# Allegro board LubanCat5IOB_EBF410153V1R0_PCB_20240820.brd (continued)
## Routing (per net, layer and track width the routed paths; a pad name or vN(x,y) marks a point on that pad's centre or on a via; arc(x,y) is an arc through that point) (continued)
VBUS5V0_TYPEC: length 27.4
  TOP w0.173: v1(24.9,99.19) v1(24.9,99.99) ; v1(27.4,99.19) v1(27.4,99.99)
  TOP w0.203: J8.A4 27.16,96.67 27.4,96.91 J8.B9 v1(27.4,99.19) ; v1(24.9,99.19) J8.B4 24.9,96.91 24.66,96.67 J8.A9
  TOP w0.254: U5.2 17.52,86.37 C74.1 17.14,88.41 17.78,89.04 17.78,90.8 v1(18.17,91.19)
  BOTTOM w0.152: v1(15.65,96.88) 15.17,96.41 C87.1 C88.1 15.17,88.59 15.23,88.54 U6.1
  BOTTOM w0.508: v1(18.17,91.19) 17.5,91.86 15.49,91.86
  vias: v1(14.65,97.88) v1(14.65,96.88) v1(15.65,97.88) v1(24.9,100.79) v1(27.4,100.79)
VCC3V3_PCIECLK: length 41.3
  TOP w0.254: C163.1 116.2,43.81 v1(115.84,44.18) 115.49,43.83 U26.1
  BOTTOM w0.381: 110.52,46.96 110.52,39.38 110.9,39 118.87,39 119.3,38.57 125.27,38.57 v1(126.26,37.58) ; 110.52,46.96 110.93,47.38 112.93,47.38 113.29,47.01 R223.1 ; 110.52,46.96 109.47,48.01 R235.1 C168.1 ; R225.1 R223.1 ; R223.1 R224.1 R226.1 116.02,45.98 116.59,45.4 C162.1 116.19,43.83 v1(115.84,44.18)
  vias: v1(127.26,37.58)
VCC3V3_PCIEX4: length 2.7
  TOP w0.254: C180.1 v1(27.56,43.81)
  BOTTOM w0.254: C194.2 R249.2 20.12,44.19
  vias: v1(26.56,43.81) v1(26.56,42.81) v1(27.56,42.81) v1(28.56,43.81) v1(28.56,42.81)
VCC3V3_SD_S3: length 19.2
  TOP w0.254: v1(150.51,19.83) 151.22,20.54 152.6,20.54 C10.1 153.97,20.54 155.15,20.54 D23.1 156.2,21.59 J24.4 ; v1(150.51,14.75) 151.15,14.11 152.65,14.11 C9.1 R285.2
  BOTTOM w0.254: v1(150.51,19.83) v1(150.51,14.75)
VCC4V0_SYS: length 304.1
  TOP w0.254: U2.5 17.78,25.52 C27.1 ; v1(166.98,96.11) 167.86,95.23 167.86,85.25 168.4,84.71 170.61,84.71 171.12,84.2 171.12,32.49 170.51,31.88 166.14,31.88 165.51,31.24 165.51,14.27 165.13,13.89 157.21,13.89 156.52,13.21 148.41,13.21 148.03,12.83 148.03,9.24 147.44,8.66 30.3,8.66 29.79,9.16 29.79,13.85 v1(29.57,14.07) ; R362.1 47.37,14.23 45.98,12.84 36.96,12.84 36.7,13.09 v2(36.7,13.88) 36.7,21.15 37.21,21.66 37.21,22.62 ; R11.1 v1(149.99,98.55)
  BOTTOM w0.254: R12.1 21.33,31.77 C20.2 21.34,24.86 21.79,24.4 26.09,24.4 26.53,23.95 v1(26.53,22.32) ; v2(36.7,13.88) 36.51,14.07 v1(29.57,14.07) ; v1(149.99,98.55) 149.99,99.79 150.5,100.29 164.98,100.29 165.81,99.47 165.81,96.62 166.32,96.11 v1(166.98,96.11)
VCC5V0_HDMI_RX: length 40.1
  TOP w0.254: R193.1 121.24,76.97 D40.2 ; Q27.2 131.89,83.49 R213.1 132.34,85.84 131.83,86.35 121.79,86.35 121.25,85.8 121.25,81.61 121.18,81.54 121.18,80.28 v1(121.11,80.21)
  BOTTOM w0.381: v1(122.11,80.21) v1(121.11,80.21) 117.73,80.21 117.07,80.87 117.07,82.04 116.31,82.8 114.94,82.8 114.31,83.43 C155.1 D45.2 111.76,84.58 111.45,84.27 110.2,84.27 109.83,84.65 J18.18
VCC5V0_USB20_HOST: length 9.5
  BOTTOM w0.508: J9.10 126.89,90.18 128.02,91.31 128.02,93.59 C286.1 C285.1
VCC5V0_USB20_HUB: length 11.5
  BOTTOM w0.508: C92.1 145.3,92.2 J10.7 J10.1
VCC5V0_USB30_OTG: length 15.9
  ART03 w0.254: J9.1 126.37,97.74 126.8,98.17 127.89,98.17 v1(128.65,98.93)
  BOTTOM w0.254: R150.1 v1(128.65,98.93)
  BOTTOM w0.508: J9.1 126.37,94.2 125.4,95.17 122.24,95.17 121.66,95.76 C91.1 C90.1
VCC5V0_USB_S0: length 21.3
  TOP w0.254: C8.1 27.56,55.42 ; U5.13 19.69,88.65 C72.1 v1(19.42,89.67) ; v1(20.46,89.67) C73.1 20.19,88.65 U5.12
  ART04 w0.254: v1(26.56,54.42) v1(27.36,54.42) v1(28.16,54.42) ; v1(26.56,55.42) v1(27.36,55.42) v1(28.16,55.42)
  BOTTOM w0.254: R4.2 C7.2 19.05,56.9 19.8,56.9 20.19,57.29 20.19,58.92 20.55,59.28 26.06,59.28 26.39,58.94 26.39,57.23 26.72,56.9
  vias: v1(5.7,91.11) v1(5.7,90.31) v1(5.7,89.51) v1(5.7,88.71) v1(5.7,87.91) v1(44.5,97.33) v1(44.5,96.33) v1(44.5,95.53) v1(44.5,94.73) v1(44.5,93.93) v1(44.5,93.13) v1(121.16,101.75) v1(121.16,100.95) v1(122.81,101.73) v1(122.81,100.93) v1(124.46,101.75) v1(124.46,100.95) v1(126.46,101.75) v1(141.1,101.5) v1(141.1,100.5) v1(142.1,100.5) v3(14.43,86.1) v3(15.23,86.1) v3(16.03,86.1) v3(16.03,85.3)
VCC12V_PCIEX4: length 3
  ART03 w0.254: v1(28.56,38.81) v1(27.56,38.81) v1(26.56,38.81) v1(26.56,39.81) 26.53,39.84
  vias: v1(27.56,39.81) v1(28.56,39.81)
VCC_1V8_S0: length 388.6
  TOP w0.203: J1.21 J1.22 46.47,14.39
  TOP w0.254: v1(111.76,73.37) 112.17,72.96 112.17,70.37 v1(111.68,69.89) ; 46.47,14.39 45.94,13.86 v2(39.7,13.86) ; v1(146.41,33.18) 146.65,33.43 Q33.1 ; R381.2 v1(63.25,73.67) ; v1(141.54,33.82) 141.69,33.97 Q34.1 ; R210.1 118.49,75.71 119.48,74.72 v1(119.48,74.31)
  ART03 w0.254: v2(38.7,13.86) 38.7,12.09 39.27,11.52 39.27,8.98 38.76,8.47 18.54,8.47 18.24,8.78 18.24,15.31 17.86,15.69 11.46,15.69 10.95,16.19 v1(10.95,16.22)
  ART03 w0.508: v1(77.37,39.69) 78.46,39.69 80.7,37.45 v1(95.32,37.45) v1(96.32,37.45)
  ART04 w0.305: v1(15.58,49.4) 15.07,48.89 15.07,46.32 14.1,45.35 11.18,45.35 10.44,44.62 10.44,20.89 10.95,20.39 v1(10.95,16.22)
  ART04 w0.381: v1(146.41,33.18) 142.18,33.18 v1(141.54,33.82) ; v1(157.1,36.92) 157.1,41.82 143.36,55.56 120.42,55.56 119.84,56.15 119.84,63.11 120.73,64 120.73,65.98 120.35,66.36 118.78,66.36 117.88,67.25 117.88,70.2 119.48,71.8 v1(119.48,74.31) 118.81,74.98 112.14,74.98 111.76,74.6 v1(111.76,73.37) 111.35,72.96 110.03,72.96 109.27,72.2 109.27,70.73 108.79,70.25 105.33,70.25 104.57,71.01 104.57,75.91 103.81,76.67 89.84,76.67 89.08,75.91 89.08,70.65 88.32,69.89 82.07,69.89 81.31,70.65 81.31,72.71 80.67,73.34 63.58,73.34 v1(63.25,73.67)
  ART04 w0.508: v1(146.41,33.18) v1(147.21,33.18) 147.65,33.63 147.65,34.79 146.89,35.55 146.08,35.55 145.31,36.31 145.31,40.25 144.4,41.16 126.59,41.16 123.67,38.24 98.53,38.24 97.74,37.45 v1(96.32,37.45) ; v1(43.59,27.62) v1(43.59,28.62) 44.17,29.21 44.17,36.59 45.19,37.61 49.28,37.61 51,39.33 74.09,39.33 74.45,39.69 v1(76.37,39.69) v1(77.37,39.69)
  BOTTOM w0.254: R273.2 16.26,50.09 v1(15.58,49.4) ; R175.1 120.89,70.62 121.41,71.14 121.41,73.28 121.04,73.65 R174.1 119.61,74.31 v1(119.48,74.31) ; Q23.1 111.05,69.66 R191.1 111.68,69.38 v1(111.68,69.89) ; v1(141.54,33.82) 142.27,34.55 R332.1 ; Q15.1 111.05,73.09 R172.1 111.76,72.89 v1(111.76,73.37) ; v1(146.41,33.18) 146.69,33.46 R329.1
  vias: v1(157.1,35.92)
VCC_1V8_S3: length 351.7
  TOP w0.203: J1.19 J1.20 46.07,15.03
  TOP w0.254: R284.1 149.38,16.51 149.38,24.07 151.87,26.56 154.74,26.56 155.27,27.1 155.27,28 154.91,28.36 152.1,28.36 151.59,28.87 v1(151.59,39.89) ; v2(39.7,14.86) 40.04,14.52 45.56,14.52 46.07,15.03
  TOP w0.381: v1(34,30.12) 43.77,30.12 v1(45.2,28.69)
  ART03 w0.254: v1(5.99,95.62) 6.76,96.38 19.1,96.38 19.61,95.87 19.61,93.51 20.14,92.98 30.32,92.98 31.15,93.82 34.77,93.82 35.2,94.25 35.2,100.22 35.46,100.47 40.36,100.47 v1(41.4,101.51)
  ART03 w0.508: v1(82.85,36.51) 95.1,36.51 v1(95.35,36.26)
  ART04 w0.381: v2(39.7,14.86) v2(38.7,14.86) 38.21,14.37 36.92,14.37 36.67,14.62 34.82,14.62 34.06,15.38 34.06,18.42 34.59,18.96 34.59,29.53 v1(34,30.12) 34.59,30.71 34.59,34.56 33.99,35.17 31.06,35.17 30.3,35.93 30.3,50.66 29.62,51.35 27.43,51.35 26.59,52.19 16.87,52.19 16.1,52.95 16.1,56.43 15.34,57.19 7.47,57.19 6.5,56.23 3.17,56.23 2.41,56.99 2.41,58.84 1.4,59.86 1.4,94.73 1.88,95.21 5.59,95.21 v1(5.99,95.62) ; v1(82.85,36.51) 78.28,36.51 76.71,38.09 72.9,38.09 71.04,36.24 45.97,36.24 45.2,35.47 v1(45.2,28.69) ; v1(118.59,33.44) 118.59,36.21 117.83,36.97 98.86,36.97 98.15,36.26 v1(95.35,36.26)
  BOTTOM w0.254: v1(151.59,39.89) 150.62,38.93 137.74,38.93 137.08,38.27 137.08,34.94 136.58,34.43 132.18,34.43 129.72,31.97 120.07,31.97 v1(118.59,33.44) 118.59,33.65 R276.1 119.4,34.44 R3.1 ; R119.1 v1(41.4,101.51)
VCC_3V3_S0: length 396.1
  TOP w0.254: R198.1 130.17,84.84 129.79,85.22 127.36,85.22 126.86,84.72 ; R198.1 130.83,83.95 v1(131.06,84.18) ; R198.1 130.49,83.62 Q25.1 ; R356.1 v1(87.12,13.86) ; R356.1 R359.1 R358.1 ; R356.1 R357.1 ; v1(11.18,56.39) 11.18,58.66 7.16,62.68 v1(7.16,64.02) ; 126.86,84.72 R196.1 127.19,83.62 Q24.1 ; 126.86,84.72 126.22,85.36 123.9,85.36 123.56,85.02 R199.1 123.89,83.62 Q26.1 ; R361.1 R360.1 76.32,14.76 75.95,15.13 v1(75.44,15.13) ; U47.5 v1(127.38,26.8) ; Q6.1 83.63,72.1 R151.1 84.08,70.58 83.57,70.08 81.54,70.08 81.03,70.58 R170.1 ; v1(10.44,72.33) 10.52,72.25 10.52,68.42 9.21,67.11 9.21,64.7 v1(8.51,64) ; R128.1 v1(152.92,99.31) ; R328.1 v1(9.28,40.52) ; U45.5 v1(119.25,26.8)
  TOP w0.381: R170.1 79.51,71.64 R363.2 v1(79.5,69.74) ; D46.2 133.53,77.21 v1(132.78,77.21) ; v1(62.19,82.13) 62.14,82.18 R383.2 ; v1(78.47,83.13) 78.86,82.74 R364.2
  ART03 w0.254: v1(152.92,99.31) 148.29,99.31 147.78,98.8 147.78,96.66 147.32,96.2 133.05,96.2 132.69,95.85 132.69,88.53 132.21,88.05 v1(131.06,88.05)
  ART04 w0.254: v1(78.47,83.13) 78.11,82.77 62.83,82.77 v1(62.19,82.13) ; v1(11.18,56.39) 11.95,55.62 13.69,55.62 14.1,55.21 14.1,51.87 ; v1(9.28,40.52) 9.09,40.71 9.09,50.56 9.5,50.97 10.11,50.97 10.52,51.37 13.61,51.37 14.1,51.87 ; 14.1,51.87 14.61,51.36 26.05,51.36 26.56,50.85 v1(26.56,49.68)
  ART04 w0.381: 34.47,9.97 J44.5 ; J44.5 33.75,10.7 ; J44.5 35.2,10.7 ; J44.5 34.47,11.43
  ART04 w0.508: v1(93.6,73.93) 94.61,72.91 v1(94.61,67.71) 94.61,62.78 95.12,62.27 109.45,62.27 109.96,62.78 v1(109.96,64.77) v1(109.96,65.77) 110.54,66.35 110.54,71.13 110.97,71.57 113.2,71.57 113.92,70.85 v1(113.92,69.21) v1(113.92,64.65) 113.92,55.64 114.94,54.62 v1(122.89,54.62) v1(123.89,54.62) 143.15,54.62 155.85,41.92 155.85,33.03 156.57,32.32 156.57,20.42 155.7,19.55 155.7,17.77 154.61,16.68 153.67,16.68 152.3,15.31 148.26,15.31 147.24,16.32 147.24,21.96 146.74,22.47 145.21,22.47 ; v1(132.78,77.21) v1(132.78,78.01) 132.34,78.45 ; 132.34,78.45 122.91,78.45 121.79,77.33 121.79,73.85 121.41,73.47 121.41,63.18 120.65,62.42 120.65,58.77 122.21,57.21 v1(122.85,57.21) v1(123.85,57.21) ; 132.34,78.45 132.54,78.65 132.54,82.71 v1(131.06,84.18) v1(131.06,88.05)
  BOTTOM w0.254: v1(93.6,73.93) 92.96,73.29 R153.1 R154.1 ; L23.1 v1(135.85,28.79) ; R157.1 93.73,66.82 v1(94.61,67.71) 94.74,67.83 R158.1 ; v1(26.56,48.68) 26.33,48.91 20.32,48.91 20.07,49.16 20.07,49.91 19.81,50.16 R272.2 C232.2 ; R179.1 v1(113.92,64.65) ; R65.2 10.74,72.33 v1(10.44,72.33) ; R100.1 C93.1 135.76,74.93 134.97,74.13 133.3,74.13 132.78,74.66 v1(132.78,77.21) ; R330.1 v1(145.61,34.55) ; v1(128.26,32.58) 128.27,32.6 R246.2 ; C216.1 v1(119.25,26.8) ; v1(11.18,56.39) 11.39,56.6 15.29,56.6 R6.2 ; L22.1 143.73,28.66 v1(143.6,28.79) ; C313.1 v1(127.38,26.8) ; v1(140.54,33.82) 140.72,34 R331.1 ; v1(78.47,83.13) 78.23,82.89 78.23,77.94 78,77.71 78,74.31 79.17,73.14 79.17,70.07 v1(79.5,69.74) ; v1(7.16,64.02) 7.19,64 v1(8.51,64) ; R178.1 v1(113.92,69.21)
  BOTTOM w0.305: v1(128.96,21.21) 128.27,21.21 L24.2
  BOTTOM w0.381: R382.2 55.63,71.4 v1(55.63,71.11)
  vias: v1(27.56,49.68) v1(27.56,48.68) v1(28.56,49.68) v1(28.56,48.68) v1(47.35,39.26) v1(48.35,39.26) v1(58.04,59.02) v1(58.04,58.02)
VCC_3V3_S3: length 322
  TOP w0.203: 44.36,16.96 44.87,17.46 J1.14 J1.13
  TOP w0.254: R87.1 18.42,84.13 v1(17.93,84.62) ; R109.1 v1(161.16,96.14) ; v2(39.7,17.86) 40.61,16.96 44.36,16.96 ; R111.2 v1(164.72,96.14) ; v1(137.29,45.23) 136.54,45.23 136.29,45.48 U44.24 ; U33.5 5.83,19.04 C235.1 4.22,18.17 v1(4.19,18.19) ; v1(139.18,45.98) 139.68,46.48 v1(139.68,51.26) ; U34.5 9.63,16.29 9.88,16.55 9.88,17.41 9.63,17.67 C236.1 v1(7.99,18.43) ; R285.1 v1(156.57,14.75)
  TOP w0.381: v1(119.77,39.19) D57.2 v1(119.04,39.93)
  ART03 w0.254: v1(164.72,96.14) 164.87,95.99 164.87,90.8 165.38,90.3 169.49,90.3 169.75,90.04 169.75,88.29 171.15,86.89 171.15,47.47 170.57,46.89
  ART03 w0.381: v1(6.95,86.91) 13.08,86.91 13.46,86.53 13.46,85.26 14.33,84.39 17.7,84.39 v1(17.93,84.62) ; v1(161.49,14.73) 161.49,18.35 162.03,18.89 162.03,30.76 162.99,31.72 170.33,31.72 171.09,32.49 171.09,46.36 170.57,46.89 156.31,46.89 v1(156.13,46.7)
  ART03 w0.508: v1(97.31,38.67) v1(96.31,38.67) 81.18,38.67 78.77,41.09 v1(77.34,41.09)
  ART04 w0.508: v1(97.31,38.67) 98.32,39.69 113.74,39.69 114.33,40.27 118.69,40.27 v1(119.04,39.93) v1(119.77,39.19) 122.45,39.19 125.62,42.36 136.27,42.36 137.29,43.37 v1(137.29,45.23) 138.04,45.98 v1(139.18,45.98) ; v1(38.71,41.21) v1(39.71,41.21) 40.06,41.21 40.94,40.32 73.13,40.32 73.89,41.09 v1(76.34,41.09) v1(77.34,41.09)
  BOTTOM w0.254: v1(161.49,14.73) 160.76,15.47 157.29,15.47 v1(156.57,14.75) ; v1(161.16,96.14) 161.65,96.62 164.24,96.62 v1(164.72,96.14) ; C212.1 C213.1 v1(139.18,45.98) ; C212.1 v1(137.29,45.23) ; C212.1 136.27,47 R353.1 ; v1(17.93,84.62) 18.58,84.62 C81.1 ; v1(156.13,46.7) 155.65,47.19 155.65,48.87 155.33,49.19 153.28,49.19 152.92,48.83 146.83,48.83 146.38,49.27 146.38,50.72 145.85,51.26 v1(139.68,51.26)
  BOTTOM w0.508: v1(38.71,41.21) 38.35,40.86 38.35,18.21 v2(38.7,17.86) v2(39.7,17.86)
  vias: v1(6.95,85.91) v1(6.95,84.65) v1(15.81,65.45) v1(15.81,64.45) v1(16.81,65.45) v1(17.81,65.45) v1(35.1,17.92) v1(36.02,17.9)
VCC_5V0_S0: length 221.7
  TOP w0.254: v1(79.53,99.18) 79.53,93.61 81.05,92.09 81.05,76.24 80.58,75.77 Q14.1 ; v1(162.29,84.3) v1(162.29,83.3) 162.3,83.32 R286.1
  TOP w0.305: U45.3 v1(120.52,29.08) ; U47.3 v1(128.65,29.08)
  ART04 w1.016: J44.3 40.51,8.66 156.12,8.66 157.38,9.92 157.38,12.41 158.82,13.85 162.75,13.85 163.32,14.42 163.32,17.31
  BOTTOM w0.254: v1(162.07,33.32) v1(149.17,33.32) ; C314.1 128.79,28.95 v1(128.65,29.08) ; R315.1 v1(163.07,32.32) ; v1(18.81,67.45) 18.05,68.21 17.27,68.21 16.76,68.72 16.76,70.42 16.43,70.75 13.59,70.75 13.21,71.13 R36.2 C225.2 ; R313.1 v1(163.07,49.7)
  BOTTOM w0.305: C217.1 120.66,28.95 v1(120.52,29.08)
  BOTTOM w0.381: C185.1 122.73,33.55 121.97,34.31 121.97,37.02 121.18,37.81 118.92,37.81 118.38,38.35 103.23,38.35 102.64,37.76 102.64,35.07 102.26,34.69 R127.1
  vias: v1(12.05,85.99) v1(12.85,85.99) v1(12.85,85.19) v1(18.81,66.45) v1(19.81,67.45) v1(19.81,66.45) v1(20.81,67.45) v1(20.81,66.45) v1(21.81,67.45) v1(21.81,66.45) v1(29,71.46) v1(29,70.46) v1(30,71.46) v1(40.78,72.61) v1(41.78,72.61) v1(90.93,99.19) v1(90.93,98.19) v1(91.93,99.19) v1(91.93,98.19) v1(101.22,101.22) v1(101.22,100.22) v1(102.22,101.22) v1(102.22,100.22) v1(126.26,32.58) v1(127.26,32.58) v1(149.17,34.32) v1(149.17,32.32) v1(162.07,68.21) v1(162.07,67.21) v1(162.07,50.7) v1(162.07,49.7) v1(162.07,48.7) v1(162.07,32.32) v1(162.87,67.21) v1(163.67,67.21)
VCC_12V: length 35
  TOP w0.254: C17.1 v1(11.34,31.2) ; v1(10.41,19.38) R319.1 11.27,20.2 Q5.2 ; v1(21.63,40.17) Q30.2 v1(22.36,39.43)
  ART03 w0.254: v1(45.14,72.58) 45.14,71.36 44.63,70.86 35.19,70.86 34.68,70.35 v1(34.68,69.81) v1(33.68,69.81)
  BOTTOM w0.254: R9.1 13.6,31 13.34,30.75 v1(13.34,30.2)
  BOTTOM w0.508: R131.1 101.9,31.71 101.9,20.01 v1(102.11,19.81) v1(102.11,18.81)
  vias: v1(10.41,18.38) v1(11.34,30.2) v1(11.34,29.2) v1(11.41,18.38) v1(12.32,37.48) v1(12.34,30.2) v1(12.34,29.2) v1(12.41,19.38) v1(12.41,18.38) v1(12.58,48.4) v1(12.58,47.4) v1(13.2,59.41) v1(13.32,37.48) v1(13.34,29.2) v1(13.41,19.38) v1(13.41,18.38) v1(13.58,54.12) v1(13.58,53.12) v1(13.58,48.4) v1(13.58,47.4) v1(13.84,36.45) v1(14.13,80.07) v1(14.13,79.07) v1(14.13,78.07) v1(14.13,77.07) v1(14.13,76.07) v1(14.2,59.41) v1(14.2,58.41) v1(14.32,37.48) v1(14.58,54.12) v1(14.58,53.12) v1(14.58,48.4) v1(14.58,47.4) v1(15.13,80.07) v1(15.13,79.07) v1(15.13,78.07) v1(15.13,77.07) v1(15.13,76.07) v1(15.2,59.41) v1(15.2,58.41) v1(15.32,37.48) v1(15.32,36.48) v1(15.58,54.12) v1(15.58,53.12) v1(16.2,59.41) v1(19.83,38.63) v1(20.83,39.63) v1(20.83,38.63) v1(21.83,38.62) v1(23.31,79.16) v1(23.31,78.16) v1(23.31,77.16) v1(46.14,72.58) v1(150.08,67.72) v1(150.08,66.72) v1(150.13,51.7) v1(150.13,50.7) v1(150.13,49.7) v1(150.83,67.72) v1(150.83,66.72) v1(151.13,51.7) v1(151.13,50.7) v1(151.12,49.7) v1(156.13,51.7) v1(156.13,50.7) v1(156.13,49.7) v1(156.13,48.7) v1(157.13,49.7) v1(157.13,48.7)
VCC_RTC: length 6.2
  TOP w0.254: D57.3 121.8,40.15 C237.1 121.96,39.05 120.65,39.05 119.94,38.34 119.52,38.34 119.17,37.99 U35.8
VCCA1V8_CODEC: length 9.9
  TOP w0.203: U16.3 17.75,76.16 v1(17.65,76.26) 18,76.61 U16.2
  TOP w0.254: v1(17.65,76.26) 17.17,76.74 17.17,78.3 17.63,78.75 17.63,81.29 17.88,81.54 R121.1
  BOTTOM w0.254: C114.1 C108.1 17.74,76.34 v1(17.65,76.26)
VCCA3V3_CODEC: length 130.5
  TOP w0.178: U16.16 v1(23.1,74.81)
  TOP w0.381: v1(1.91,85.88) 1.5,85.48 1.5,61.71 2.24,60.97 v1(6.32,60.97)
  ART03 w0.254: v1(39.01,96.39) 39.01,93.9 38.4,93.28 31.27,93.28 30.48,92.5 19.41,92.5 18.97,92.93 18.97,95.14 18.34,95.77 7.16,95.77 6.38,94.99 5.28,94.99 4.9,94.6 4.9,91.92 v1(4.37,91.39)
  ART03 w0.381: v1(1.91,85.88) 1.3,86.49 1.3,87.44 1.88,88.03 1.88,90.24 3.03,91.39 v1(4.37,91.39)
  BOTTOM w0.254: C124.1 C109.1 C110.1 22.23,74.05 R112.2 ; R113.2 v1(39.01,96.39) ; v1(4.37,91.39) 3.43,91.39 2.92,90.88 R125.1
  BOTTOM w0.305: v1(23.1,74.81) 23.24,74.67 R112.2
  BOTTOM w0.381: v1(23.1,74.81) 23.7,75.4 24.36,75.4 25.2,76.24 27.3,76.24 28.07,75.48 28.07,73.12 27.56,72.61 27.56,69.46 27.1,69 27.1,62.14 26.52,61.56 6.91,61.56 v1(6.32,60.97)
VCCA_1V8_S0: length 48
  TOP w0.203: 45.67,15.76 J1.18 J1.17
  TOP w0.254: v1(32.69,60.44) 32.69,60.91 33.2,61.42 36.8,61.42 38.23,62.85 R336.1 ; v1(39.73,18.76) 38.58,18.76 38.23,18.4 38.23,16.34 v2(38.7,15.86) v2(39.7,15.86) 40.31,15.25 45.16,15.25 45.67,15.76
  BOTTOM w0.305: J41.1 55.62,10.83 D24.1 55.62,15.44 54.99,16.07 53.39,16.07 52.63,16.83 43.46,16.83 42.85,17.44 42.85,18.15 42.24,18.76 v1(39.73,18.76)
  vias: v1(21.01,68.45) v1(21.81,68.45)
VCCA_3V3_S0: length 77.1
  TOP w0.203: J1.15 J1.16 45.27,17.76
  TOP w0.254: R77.1 63.75,71.64 64.01,71.39 64.01,68.19 64.26,67.93 65.74,67.93 65.99,67.68 65.99,66.05 65.41,65.47 65.41,52.64 64.87,52.11 57.84,52.11 57.45,51.73 57.45,39.46 56.72,38.72 52.17,38.72 51.66,38.22 51.66,31.66 51.16,31.16 45.59,31.16 45.09,31.66 45.09,35.91 44.58,36.41 v1(39.75,36.41) ; v2(39.7,16.86) v2(38.7,16.86)
  vias: v1(21.01,69.45) v1(21.81,69.45)
VDD_LCD0_3V3: length 11.7
  TOP w0.254: J14.5 8.26,81.07 ; 9.25,81.02 9.61,80.65 9.61,77.56 v1(9.13,77.07) ; 8.33,81.57 J14.4
  BOTTOM w0.254: v1(9.13,77.07) 9.65,76.56 11.33,76.56 11.65,76.87 11.65,77.45 R301.1 R303.1
  vias: v1(7.95,89.91) v1(7.95,88.91) v1(7.95,87.91)
VDD_LCD0_5V:
  vias: v1(6.95,89.91) v1(6.95,88.91) v1(6.95,87.91)
VDD_LCD1_3V3: length 14.7
  BOTTOM w0.254: R304.1 R302.1 10.76,69.33 9.25,69.33 9.04,69.53 9.04,70.35 8.82,70.57 J15.5
  BOTTOM w0.508: 5.97,70.3 5.74,70.07 5.74,66.64 6.71,65.67 9.59,65.67 9.81,65.45
  vias: v1(9.69,65.41) v1(9.69,64.41) v1(10.69,65.41) v1(10.69,64.41)
VDD_LCD1_5V: length 2
  BOTTOM w0.254: 7.47,66.72 7.01,67.17 J15.1
  vias: v1(18.81,65.45) v1(18.81,64.45) v1(19.81,65.45) v1(19.81,64.45)
AUTO_PWRON_EN: length 3.2
  TOP w0.178: R362.2 47.37,16.4 46.87,16.9 J1.24
BAT_RTC: length 6.4
  TOP w0.305: J26.1 113.6,41.32 115.78,41.32 D59.1 C238.1 118.31,41.1 D57.1
CAM0_NRST: length 63.7
  TOP w0.152: v1(169.11,70.35) 168.11,70.35 167.61,70.85 J32.22 ; U44.5 v1(133.69,50.98)
  ART03 w0.152: v1(169.11,70.35) 169.11,49.94 168.38,49.2 155.08,49.2 154.75,48.86 154.75,48.32 v1(154.13,47.7)
  BOTTOM w0.152: v1(133.69,50.98) 134.46,50.21 144.22,50.21 144.53,49.91 144.53,48.13 144.95,47.7 v1(154.13,47.7)
CAM0_PWDN: length 64.8
  TOP w0.152: v1(155.13,48.7) 155.83,48 160.35,48 160.73,48.39 160.73,53.62 162.05,54.94 162.05,58.23 161.52,58.77 161.52,68.62 161.14,69 160.32,69 160.02,69.31 160.02,74.62 160.32,74.93 164.19,74.93 164.77,74.35 J32.15 ; v1(136.64,50.94) 136.13,50.43 134.75,50.43 134.34,50.84 U44.4
  BOTTOM w0.152: v1(155.13,48.7) 154.69,48.26 145.92,48.26 145.41,48.77 145.41,50.33 145.07,50.67 136.91,50.67 v1(136.64,50.94)
CAM1_NRST: length 80.3
  TOP w0.152: U44.7 v1(132.39,50.98)
  ART03 w0.152: v1(154.13,46.7) 154.54,47.11 155.65,47.11 156.31,47.77 170.05,47.77 170.56,48.28 170.56,80.53 170.24,80.85 v1(168.1,80.85)
  BOTTOM w0.152: v1(168.1,80.85) 167.6,80.35 J33.22 ; v1(154.13,46.7) 143.51,46.7 143.13,47.08 143.13,48.89 142.82,49.2 133.19,49.2 132.39,50 v1(132.39,50.98)
CAM1_PWDN: length 73.2
  TOP w0.152: v1(133.69,49.98) 133.04,50.63 U44.6
  ART03 w0.152: v1(169.78,76.33) 170.1,76.01 170.1,48.58 169.78,48.26 155.68,48.26 v1(155.13,47.7)
  BOTTOM w0.152: v1(133.69,49.98) 133.97,49.71 143.59,49.71 143.89,49.4 143.89,47.62 144.27,47.24 154.67,47.24 v1(155.13,47.7) ; v1(169.78,76.33) 169.77,76.34 167.6,76.34 167.1,76.85 J33.15
CAM2_NRST: length 54.1
  TOP w0.152: U44.9 v1(131.09,50.98) ; J34.22 167.61,53.46 v1(168.11,52.96)
  BOTTOM w0.152: v1(131.09,50.98) 130.47,50.98 129.92,50.43 129.92,47.89 130.56,47.26 133.17,47.26 133.48,46.95 133.48,44.8 133.78,44.5 160.4,44.5 161.86,45.95 162.69,45.95 163.93,47.19 166.7,47.19 167.13,47.62 167.13,51.97 v1(168.11,52.96)
CAM2_PWDN: length 49
  TOP w0.152: v1(155.13,46.7) 155.77,47.34 161.16,47.34 161.47,47.65 161.47,53.16 162.81,54.51 162.81,57.23 163.15,57.56 164.52,57.56 165.12,56.96 J34.15 ; U44.8 v1(131.74,50.09)
  BOTTOM w0.152: v1(131.74,50.09) 131.74,49.38 132.45,48.67 142.06,48.67 142.37,48.36 142.37,46.45 142.71,46.1 154.53,46.1 v1(155.13,46.7)
CAM3_NRST: length 61.6
  TOP w0.152: U44.11 v1(129.79,50.98)
  BOTTOM w0.152: v1(129.79,50.98) 129.79,51.45 130.05,51.7 131.32,51.7 131.57,51.45 131.57,50.69 131.06,50.18 131.06,48.78 131.66,48.18 141.43,48.18 141.73,47.88 141.73,45.89 142.08,45.54 159.89,45.54 160.91,46.56 160.91,54.28 160.07,55.12 160.07,62.53 160.49,62.96 161.34,62.96 161.65,63.26 164.57,63.26 164.87,62.96 J35.22
CAM3_PWDN: length 60.6
  TOP w0.152: U44.10 v1(130.44,50.18)
  BOTTOM w0.152: v1(130.44,50.18) 130.43,50.17 130.43,48.4 131.13,47.7 140.92,47.7 141.22,47.4 141.22,45.35 141.57,45.01 160.25,45.01 161.42,46.18 161.42,54.51 160.66,55.27 160.66,61.47 160.96,61.77 164.54,61.77 164.83,61.48 164.83,59.7 165.08,59.46 J35.15
CAM4_NRST: length 43.9
  TOP w0.152: v1(160.38,37.46) 161.3,36.55 163.73,36.55 164.21,36.06 J36.22 ; U44.14 v1(129.79,45)
  BOTTOM w0.152: v1(160.38,37.46) 160.53,37.61 160.53,39.69 160.22,39.99 159.28,39.99 158.98,40.3 158.98,42.69 158.64,43.03 131.45,43.03 129.79,44.69 v1(129.79,45)
CAM4_PWDN: length 42.3
  TOP w0.152: v1(129.79,44) 129.14,44.65 U44.13 ; v1(160.02,39.38) 161.81,39.38 162.56,40.13 163.19,40.13 163.76,39.56 J36.15
  BOTTOM w0.152: v1(129.79,44) 131.27,42.52 158.12,42.52 158.42,42.21 158.42,39.69 158.72,39.38 v1(160.02,39.38)
CAM5_NRST: length 36.8
  TOP w0.152: U44.16 v1(131.09,45)
  BOTTOM w0.152: v1(131.09,45) 132.02,44.07 160.51,44.07 162.01,45.56 J37.22
CAM5_PWDN: length 39.5
  TOP w0.152: v1(131.09,44) 130.44,44.65 U44.15
  BOTTOM w0.152: v1(131.09,44) 131.55,43.53 160.49,43.53 161.42,44.46 163.76,44.46 164.39,43.84 164.39,42.45 164.77,42.06 J37.15
CAN1_H: length 47.7
  TOP w0.203: U45.7 121.79,26.31 121.28,26.83 121.28,27.61 120.75,28.14 118.17,28.14 R333.1 117.54,28.14 116.39,28.14 115.32,27.07 112.39,27.07 111.17,25.84 111.17,19.61 110.34,18.79 107.16,18.79 105.19,16.81 98.82,16.81 98.17,16.17 98.17,15.52 D74.2 98.04,14.87 98.04,11.3 97.38,10.64 94.5,10.64 94.03,11.11 94.03,12.83 94.25,13.05 J40.1
CAN1_L: length 47.5
  TOP w0.203: J40.2 93.3,13.05 93.62,12.72 93.62,10.95 94.34,10.24 97.6,10.24 98.48,11.12 98.48,14.8 D75.2 98.58,15.36 98.58,15.99 98.99,16.41 105.36,16.41 107.33,18.38 110.51,18.38 111.57,19.45 111.57,25.67 112.56,26.66 115.48,26.66 116.56,27.74 117.58,27.74 R333.2 118.13,27.73 120.59,27.73 120.87,27.44 120.87,26.87 120.52,26.52 U45.6
CAN1_RX_M1: length 127.1
  TOP w0.152: U45.4 v1(119.25,28.87) ; J3.30 48.07,67.32 v2(47.67,66.92) ; v1(45.29,48.26) 45.29,38.84 46.84,37.3 46.84,33.59 v1(47.28,33.16)
  ART03 w0.152: v1(47.28,33.16) 47.75,32.68 58.52,32.68 59.99,31.21 64.74,31.21 65.35,30.6 75.31,30.6 75.62,30.9 75.62,34.66 75.92,34.97 101.55,34.97 103.43,36.84 117.09,36.84 118.11,35.83 120.73,35.83 121.03,35.52 121.03,31.82 120.73,31.51 119.56,31.51 119.25,31.21 v1(119.25,28.87)
  ART04 w0.152: v1(45.29,48.26) 45.73,48.69 45.73,60.37 47.07,61.71 47.07,65.65 47.67,66.26 v2(47.67,66.92)
CAN1_TX_M1: length 126.8
  TOP w0.152: U45.1 v1(123.06,29.08) ; J3.28 v2(47.67,67.76) ; v1(48.28,33.16) 47.8,33.63 47.8,37.2 45.75,39.26 45.75,48.81 v1(45.29,49.26)
  ART03 w0.152: v1(48.28,33.16) 59.04,33.16 60.05,32.15 64.77,32.15 65.53,31.38 74.55,31.38 74.8,31.64 74.8,35.19 75.18,35.57 101.37,35.57 103.28,37.48 120.9,37.48 121.41,36.97 122.5,36.97 122.81,36.67 122.81,32.15 123.06,31.89 v1(123.06,29.08)
  ART04 w0.152: v1(45.29,49.26) 45.29,60.96 46.18,61.84 46.18,65.39 47.25,66.47 47.25,67.34 v2(47.67,67.76)
CAN2_H: length 48.9
  TOP w0.203: U47.7 129.92,26.41 129.5,26.84 129.5,27.64 128.99,28.15 126.14,28.15 R355.1 125.59,28.17 124.88,28.17 124.29,27.58 124.29,24.04 123.89,23.64 115.19,23.64 114.54,22.99 114.54,17.97 113.78,17.21 107.88,17.21 107.06,16.39 107.06,15.52 D76.2 106.97,14.83 106.97,11.05 106.56,10.64 103.22,10.64 102.87,10.99 102.87,12.78 103.14,13.05 J45.1
CAN2_L: length 48.7
  TOP w0.203: J45.2 100.84,13.05 102.12,13.05 102.46,12.71 102.46,10.82 103.05,10.24 106.73,10.24 107.37,10.88 107.37,14.8 D77.2 107.47,15.36 107.47,16.22 108.05,16.8 113.95,16.8 114.95,17.8 114.95,22.82 115.36,23.23 124.06,23.23 124.7,23.88 124.7,27.42 125.05,27.76 125.53,27.76 R355.2 126.16,27.75 128.82,27.75 129.09,27.48 129.09,26.88 128.65,26.44 U47.6
CAN2_RX_M0: length 124.8
  TOP w0.152: J3.36 v2(49.27,67.76) ; U47.4 v1(127.38,29.08)
  ART03 w0.152: v1(47.29,47.26) 84.94,47.26 86.06,48.38 99.21,48.38 100.51,47.08 102.82,47.08 103.78,48.05 112.29,48.05 112.58,47.76 113.42,47.76 113.83,47.34 116.16,47.34 116.36,47.54 127.46,47.54 127.76,47.23 127.76,29.46 v1(127.38,29.08)
  ART04 w0.152: v2(49.27,67.76) 48.89,67.38 48.89,47.59 48.56,47.26 v1(47.29,47.26)
CAN2_TX_M0: length 127
  TOP w0.152: J3.34 48.87,67.32 v2(48.47,66.92)
  TOP w0.173: U47.1 v1(131.19,29.08)
  ART03 w0.152: v1(47.29,48.26) 47.79,47.77 78.08,47.77 78.56,48.25 79.86,48.25 80.44,47.67 84.35,47.67 85.62,48.94 99.87,48.94 100.58,48.22 102.77,48.22 103.33,48.78 113.41,48.78 114.05,48.15 115.4,48.15 115.66,48.4 127.99,48.4 128.3,48.1 128.3,41.95 128.69,41.56 128.69,30.01 128.99,29.71 130.57,29.71 v1(131.19,29.08)
  ART04 w0.152: v1(47.29,48.26) 46.76,48.79 46.76,60.31 48.16,61.71 48.16,66.6 v2(48.47,66.92)
CTP0_INT: length 134
  TOP w0.152: J4.44 v2(76.44,67.76) ; J14.11 v1(8.13,78.07)
  ART04 w0.152: v2(76.44,67.76) 76.01,67.32 76.01,67.11 74.95,66.06 74.95,53.86 73.87,52.77 53.69,52.77 52.49,53.97 52.49,65.64 52.86,66 52.86,68.14 51.28,69.71 49.28,69.71 48.98,70.02 48.98,71.16 48.67,71.47 46.99,71.47 46.69,71.77 46.69,73.6 46.36,73.93 46.05,73.93 45.76,74.22 45.76,80.82 46.69,81.75 46.69,85.92 45.21,87.39 41.78,87.39 39.75,85.36 39.75,77.33 39.4,76.98 28.8,76.98 28.32,77.45 28.32,78.69 v1(29.09,79.45)
  BOTTOM w0.152: R301.2 10.4,77.74 10.31,77.64 8.56,77.64 v1(8.13,78.07) 8.56,78.51 9.22,78.51 9.58,78.86 9.58,79.16 9.93,79.52 12.32,79.52 13.23,78.6 17.32,78.6 18.69,79.97 24.43,79.97 25.02,79.39 29.03,79.39 v1(29.09,79.45)
CTP0_RST: length 171.6
  TOP w0.152: U44.17 131.74,46.75 131.44,47.06 127.13,47.06 126.78,46.71 v1(126.78,44.33) ; v1(9.58,53.4) 9.58,58.54 6.38,61.74 2.97,61.74 2.36,62.35 2.36,75.87 2.67,76.17 3.76,76.17 4.06,76.48 4.06,78.08 4.37,78.38 5.69,78.38 5.99,78.08 5.99,77.88 6.3,77.57 J14.12 8.63,77.57 v1(9.13,78.07)
  ART03 w0.152: v1(126.78,44.33) 124.08,47.03 116.74,47.03 116.33,46.62 108.28,46.62 107.31,45.66 103.28,45.66 102.84,46.09 100.3,46.09 99.69,46.7 37.92,46.7 36.45,48.17 30.73,48.17 29.72,49.19 26.14,49.19 25.76,48.81 12.32,48.81 12.01,49.11 12.01,49.65 11.3,50.36 11.3,53 10.9,53.4 v1(9.58,53.4)
  BOTTOM w0.152: v1(9.13,78.07) 9.48,78.07 10.05,78.64 10.82,78.64 R303.2
CTP1_INT: length 148
  TOP w0.152: v2(76.44,66.92) 76.84,67.32 J4.46
  ART03 w0.152: v1(5.97,73.57) 7.62,73.57 7.92,73.87 7.92,76.16 8.31,76.55 16.46,76.55 16.76,76.24 16.76,72.13 17.22,71.67 17.22,70.37 17.6,69.99 21.89,69.99 22.2,70.3 22.2,73.07 22.61,73.47 28.57,73.47 29.09,73.99 v1(29.09,75.45)
  ART04 w0.152: v2(76.44,66.92) 75.4,65.88 75.4,53.64 74.08,52.33 53.43,52.33 52.09,53.66 52.09,67.94 50.9,69.13 48.74,69.13 48.44,69.43 48.44,70.07 48.13,70.37 46.63,70.37 45.54,71.47 45.54,72.96 45.21,73.29 45.21,80.99 46.18,81.96 46.18,85.66 45.09,86.76 41.78,86.76 40.77,85.74 40.77,76.44 40.21,75.88 31.17,75.88 30.73,75.45 v1(29.09,75.45)
  BOTTOM w0.152: R302.2 10.35,70.75 9.63,71.47 9.63,72.2 8.26,73.57 J15.11 v1(5.97,73.57)
CTP1_RST: length 176.9
  TOP w0.152: v1(124.78,44.33) 124.78,47.87 125.09,48.17 132.74,48.17 133.04,47.87 U44.19
  ART03 w0.152: v1(124.78,44.33) 123.61,45.51 108.99,45.51 107.62,44.13 100.05,44.13 98.3,45.89 36.63,45.89 35.76,46.75 29.77,46.75 29.29,47.23 20.55,47.23 20.27,46.95 10.46,46.95 10.16,47.26 10.16,50.82 v1(9.58,51.4)
  BOTTOM w0.152: R304.2 11.58,71.36 10.32,71.36 9.98,71.69 9.98,72.51 10.21,72.73 10.21,73.98 9.99,74.2 9.44,74.2 9.22,73.98 8.72,73.98 8.64,74.07 J15.12 3.33,74.07 2.79,73.53 2.79,60.98 3.23,60.55 4.78,60.55 5.33,59.99 8.99,59.99 9.58,59.41 9.58,54.08 10.16,53.49 10.16,51.99 v1(9.58,51.4)
DGB_RX: length 7.2
  TOP w0.152: R291.1 4.25,16.14 v1(4.19,16.19)
  BOTTOM w0.152: J25.2 5.38,17.72 5.68,17.41 D55.1 4.63,16.64 v1(4.19,16.19)
DGB_TX: length 6.9
  TOP w0.152: v1(4.19,19.19) 4.2,19.2 R290.1
  BOTTOM w0.152: v1(4.19,19.19) 5.44,19.19 5.68,19.44 D56.1 4.45,20.06 4.25,20.26 J25.1
EARPHONE_CTL: length 206.2
  TOP w0.152: v1(48.06,12.2) 48.6,12.74 66.52,12.74 67.44,11.83 67.44,10.35 67.74,10.05 70.61,10.05 72.87,12.31 81.89,12.31 82.5,12.92 82.5,15.94 82.04,16.4 J2.72
  ART03 w0.152: v1(5.38,96.31) 6.35,97.27 20.29,97.27 20.85,96.71 20.85,93.82 21.26,93.41 29.88,93.41 v1(30.96,94.49)
  BOTTOM w0.152: v1(48.06,12.2) 46.98,13.27 36.42,13.27 36.11,13.59 10.92,13.59 10.49,14.02 10.49,15.52 9.97,16.04 9.97,21.27 9.53,21.72 4.54,21.72 2.67,23.59 2.67,59.18 1.65,60.2 1.65,85 2.9,86.25 4.04,86.25 4.37,86.58 4.37,90.39 5.33,91.35 5.33,96.26 v1(5.38,96.31)
  BOTTOM w0.203: v1(30.96,94.49) 31.42,94.95 31.42,96.19 31.75,96.52 R326.2
EKEY_PETN0: length 11.4
  BOTTOM w0.165: C252.2 134.49,61.67 134.85,62.03 134.85,65.76 133.18,67.44 133.18,68.87 132.92,69.13 132.92,69.79 133.18,70.05 133.18,70.43 133.08,70.54 J13.37
EKEY_PETP0: length 11.2
  BOTTOM w0.165: C251.2 135.51,61.67 135.15,62.03 135.15,65.88 133.47,67.56 133.47,70.43 133.58,70.54 J13.35
FAN_CTRL: length 30.6
  TOP w0.152: v2(80.52,28.34) 80.52,27.73 80.14,27.35 80.14,23.89 80.44,23.59 J2.63
  ART03 w0.152: v2(80.52,28.34) 88.52,28.34 89.66,29.48 v1(96.19,29.48)
  BOTTOM w0.152: R133.1 96.34,25.29 96.19,25.44 v1(96.19,29.48)
FUSB302_INT: length 137.5
  TOP w0.152: v2(80.84,16.85) 81.24,17.25 J2.68 ; R87.2 19.46,83.49 v1(19.46,84.34) 19.54,84.34 19.69,84.5 U5.5
  ART04 w0.152: v2(80.84,16.85) 81.71,16.85 82.02,17.16 82.02,23.39 82.47,23.84 82.47,30.88 82.78,31.18 84.18,31.18 85.09,32.1 85.09,46.12 84.79,46.42 50.47,46.42 49.73,45.68 42.62,45.68 42.01,46.29 42.01,67.02 39.12,69.92 39.12,72.89 38.61,73.4 33.2,73.4 32.59,74.01 23.11,74.01 22.61,74.51 22.61,80.25 22.3,80.56 20.12,80.56 19.81,80.86 19.81,83.99 v1(19.46,84.34)
GMAC0_MCLKINOUT: length 81.8
  TOP w0.173: J1.66 55.27,16.62 55.63,16.27 61.23,16.27 61.65,16.69 61.65,17.31 v2(61.27,17.69)
  BOTTOM w0.173: v2(61.27,17.69) 61.27,25.53 56.35,30.46 56.35,60.4 56.97,61.03 59.17,61.03 59.51,61.37 59.51,66.45 59.17,66.79 54.51,66.79 54.23,67.07 54.23,68.7 54.51,68.98 55.83,68.98 56.01,69.15 56.01,70.65 58.04,72.68 58.04,74.18 57.28,74.94 R67.1 R68.1
GMAC0_MDC: length 100
  TOP w0.152: v1(66.17,32.92) 65.53,32.29 65.53,26.23 65.23,25.92 63.14,25.92 62.74,25.52 62.74,23.51 63.04,23.21 63.04,20.61 62.79,20.36 61.81,20.36 61.27,19.82 J1.96 ; U3.13 48.4,78.87 47.32,79.95 v1(47.32,80.37)
  ART03 w0.152: v1(48.28,34.28) 48.43,34.13 64.96,34.13 v1(66.17,32.92)
  BOTTOM w0.152: v1(48.28,34.28) 47.64,34.91 44.2,34.91 43.79,35.32 43.79,55.34 43.54,55.59 40.41,55.59 40.18,55.82 40.18,77.56 40.49,77.87 46.29,77.87 47.32,78.9 v1(47.32,80.37) 47.15,80.53 R61.2
GMAC0_MDIO: length 100.7
  TOP w0.152: U3.14 48.14,78.47 47.68,78.93 46.74,78.93 v1(46.2,78.4) ; J1.98 61.67,19.66 61.98,19.96 63.05,19.96 63.37,20.28 63.37,23.48 63.09,23.76 63.09,25.26 63.4,25.57 65.68,25.57 66.03,25.91 66.03,31.78 v1(66.17,31.92)
  ART03 w0.152: v1(47.28,34.28) 47.86,33.7 59.84,33.7 60.3,33.24 64.85,33.24 v1(66.17,31.92)
  BOTTOM w0.152: R62.2 46.72,78.91 v1(46.2,78.4) 45.72,78.88 40.08,78.88 39.55,78.35 39.55,63.06 39.12,62.63 39.12,55.54 39.6,55.06 42.88,55.06 43.1,54.83 43.1,35.09 43.91,34.28 v1(47.28,34.28)
GMAC0_RSTN: length 60.7
  TOP w0.152: J4.48 77.24,65.98 77.01,65.75 67.54,65.75 67.23,66.05 67.23,68.87 66.93,69.18 65.56,69.18 65.25,69.48 65.25,73.57 64.92,73.91 v1(64.92,78.37)
  BOTTOM w0.152: D7.1 41.88,79.98 41.88,84.5 42.14,84.75 45.26,84.75 45.92,84.09 63.12,84.09 63.45,83.76 63.45,78.8 63.88,78.37 v1(64.92,78.37)
GMAC0_RXCLK: length 69.7
  TOP w0.173: v2(60.86,19.78) 60.81,19.83 59.61,19.83 59.27,19.49 J1.86 ; R56.1 v1(52.41,71.01)
  BOTTOM w0.173: R59.1 52.45,71.05 v1(52.41,71.01) 53.61,69.8 53.61,66.34 53.82,66.13 54.18,66.13 54.38,65.93 54.38,65.67 54.59,65.47 54.87,65.47 55.07,65.67 55.07,65.93 55.28,66.13 55.58,66.13 55.78,65.93 55.78,65.19 55.98,64.99 56.27,64.99 56.47,65.19 56.47,65.93 56.67,66.13 56.96,66.13 57.16,65.93 57.16,65.19 57.36,64.99 57.65,64.99 57.85,65.19 57.85,65.93 58.05,66.13 58.6,66.13 58.78,65.96 58.78,63.45 58.43,63.11 56.16,63.11 55.82,62.76 55.82,29.97 60.86,24.93 v2(60.86,19.78)
GMAC0_RXD0: length 69.3
  TOP w0.173: v2(59.67,16.85) 60.07,17.25 J1.90 ; R51.1 v1(50.37,71.01)
  BOTTOM w0.173: R48.2 50.42,71.05 v1(50.37,71.01) 50.37,68.56 50.65,68.29 51.61,68.29 52.05,67.85 52.05,65.94 52.35,65.65 52.35,64.07 52.98,63.44 52.98,58.76 53.19,58.56 54.32,58.56 54.52,58.36 54.52,58.07 54.32,57.87 53.19,57.87 52.98,57.67 52.98,57.38 53.19,57.18 54.32,57.18 54.52,56.97 54.52,56.69 54.32,56.49 53.19,56.49 52.98,56.28 52.98,56 53.19,55.8 54.32,55.8 54.52,55.59 54.52,29.6 60.05,24.07 60.05,19.29 60.26,19.09 60.5,19.09 60.71,18.89 60.71,18.6 60.5,18.4 60.26,18.4 60.05,18.2 60.05,17.23 v2(59.67,16.85)
GMAC0_RXD1: length 68.2
  TOP w0.173: R52.1 v1(49.36,71.01) ; J1.88 v2(59.67,17.69)
  BOTTOM w0.173: R49.2 49.4,71.05 v1(49.36,71.01) 49.65,70.71 49.65,66.57 50.12,66.1 51.05,66.1 51.82,65.33 51.82,63.79 52.35,63.26 52.35,55.12 52.55,54.91 53.75,54.91 53.95,54.71 53.95,54.43 53.75,54.22 52.55,54.22 52.35,54.02 52.35,53.72 52.55,53.52 53.79,53.52 54,53.32 54,51.64 53.79,51.43 52.94,51.43 52.72,51.21 52.72,50.92 52.89,50.74 53.79,50.74 54,50.54 54,50.25 53.79,50.05 53.02,50.05 52.82,49.85 52.82,49.56 53.02,49.36 53.79,49.36 54,49.16 54,29.38 59.49,23.89 59.49,17.88 v2(59.67,17.69)
GMAC0_RXD2: length 66.9
  TOP w0.173: J1.94 60.87,17.25 v2(60.47,16.85) ; R54.1 v1(48.34,71.01)
  BOTTOM w0.173: v1(48.34,71.01) 48.26,70.93 R58.1 48.89,69.61 48.89,66.47 49.8,65.57 50.78,65.57 51.31,65.04 51.31,63.34 51.82,62.83 51.82,52.9 52.02,52.7 53.04,52.7 53.24,52.5 53.24,52.21 53.04,52.01 52.02,52.01 51.82,51.81 51.82,49.08 52.16,48.73 53.04,48.73 53.47,48.3 53.47,29.02 58.95,23.54 58.95,16.7 59.31,16.35 59.97,16.35 v2(60.47,16.85)
GMAC0_RXD3: length 67.9
  TOP w0.173: R55.1 v1(47.33,71.01) ; J1.92 v2(60.47,17.69)
  BOTTOM w0.173: v2(60.47,17.69) 60.88,17.28 60.88,15.99 60.71,15.81 58.9,15.81 58.47,16.25 58.47,23.27 52.94,28.8 52.94,47.67 52.63,47.97 51.55,47.97 51.21,48.32 51.21,62.37 50.29,63.29 50.29,64.56 49.83,65.01 49.4,65.01 48.09,66.32 48.09,67.88 47.37,68.6 47.37,70.96 v1(47.33,71.01) 48.22,71.91 R50.2
GMAC0_RXDV_CRS: length 70
  TOP w0.173: R57.1 v1(51.39,71.01) ; v2(60.48,20.49) 59.28,20.49 58.87,20.08 J1.84
  BOTTOM w0.173: v2(60.48,20.49) 60.48,24.55 55.24,29.78 55.24,59.13 55.04,59.34 53.75,59.34 53.54,59.54 53.54,59.82 53.75,60.03 55.04,60.03 55.24,60.23 55.24,60.51 55.04,60.72 53.75,60.72 53.54,60.92 53.54,61.21 53.75,61.41 55.04,61.41 55.24,61.61 55.24,61.9 55.04,62.1 53.75,62.1 53.54,62.3 53.54,62.59 53.75,62.79 55.04,62.79 55.24,62.99 55.24,63.28 55.04,63.48 53.75,63.48 53.54,63.68 53.54,63.98 53.75,64.19 54.31,64.19 54.51,64.39 54.51,64.67 54.31,64.88 53.55,64.88 53.09,65.34 53.09,67.96 51.39,69.66 v1(51.39,71.01) 51.44,71.05 R60.1
GMAC0_TXCLK: length 81.9
  TOP w0.173: v2(57.65,20.46) 56.65,20.46 56.47,20.29 J1.72 ; U3.20 49.14,76.07 48.52,75.44 v1(48.52,75.37)
  BOTTOM w0.173: v2(57.65,20.46) 57.65,22.17 51.84,27.98 51.84,39.38 51.56,39.66 50.29,39.66 50.09,39.87 50.09,40.17 50.29,40.37 51.59,40.37 51.79,40.57 51.79,40.86 51.59,41.06 50.29,41.06 50.09,41.26 50.09,41.55 50.29,41.75 51.59,41.75 51.79,41.95 51.79,42.24 51.59,42.44 50.29,42.44 50.09,42.64 50.09,42.93 50.29,43.13 51.59,43.13 51.79,43.34 51.79,43.62 51.59,43.82 50.29,43.82 50.09,44.03 50.09,44.31 50.29,44.51 51.59,44.51 51.79,44.72 51.79,45 51.59,45.21 50.29,45.21 50.09,45.41 50.09,45.69 50.29,45.9 51.59,45.9 51.79,46.1 51.79,46.39 51.59,46.59 50.29,46.59 50.09,46.79 50.09,61.79 49.78,62.09 48.62,62.09 48.34,62.37 48.34,64.35 47.22,65.47 45.97,65.47 45.67,65.78 45.67,67.98 46.71,69.03 46.71,72.76 48.13,74.18 48.13,74.97 v1(48.52,75.37)
GMAC0_TXD0: length 82.4
  TOP w0.173: v1(47.52,75.37) 47.52,75.74 48.02,76.24 48.02,76.39 48.49,76.87 U3.18 ; J1.74 v2(56.87,19.96)
  BOTTOM w0.173: v1(47.52,75.37) 47.05,74.89 44.87,74.89 44.58,74.6 44.58,72.53 44.07,72.02 44.07,66.51 43.53,65.97 43.53,63.29 43.81,63.01 44.49,63.01 44.83,62.66 44.83,61.88 44.66,61.71 44.22,61.71 43.92,61.41 43.92,60.64 44.22,60.34 47.22,60.34 47.5,60.06 47.5,50.03 47.88,49.65 47.88,49.2 48.08,49 48.59,49 48.79,48.8 48.79,48.51 48.59,48.31 48.08,48.31 47.88,48.1 47.88,47.82 48.08,47.62 48.59,47.62 48.79,47.41 48.79,47.13 48.59,46.93 48.08,46.93 47.88,46.72 47.88,46.44 48.08,46.23 48.59,46.23 48.79,46.03 48.79,45.75 48.59,45.54 48.08,45.54 47.88,45.34 47.88,45.06 48.08,44.85 48.59,44.85 48.79,44.65 48.79,44.36 48.59,44.16 48.08,44.16 47.88,43.96 47.88,43.67 48.08,43.47 48.59,43.47 48.79,43.27 48.79,42.98 48.59,42.78 48.08,42.78 47.88,42.58 47.88,42.29 48.08,42.09 48.59,42.09 48.79,41.89 48.79,41.6 48.59,41.4 48.08,41.4 47.88,41.2 47.88,40.91 48.08,40.71 48.59,40.71 48.79,40.51 48.79,40.22 48.59,40.02 48.08,40.02 47.88,39.81 47.88,38.83 48.31,38.39 50.29,38.39 50.6,38.09 50.6,27.65 55.5,22.75 55.5,20.21 55.74,19.96 v2(56.87,19.96)
GMAC0_TXD1: length 82
  TOP w0.173: v2(56.07,17.69) 57.05,17.69 57.27,17.92 J1.76 ; v1(47.52,76.37) 47.52,76.5 48.28,77.27 U3.17
  BOTTOM w0.173: v1(47.52,76.37) 47.09,75.94 43.54,75.94 43.31,75.71 43.31,67.2 43,66.89 43,59.9 43.2,59.69 45.95,59.69 46.15,59.49 46.15,59.21 45.95,59 43.2,59 43,58.8 43,58.36 43.21,58.16 46.59,58.16 46.76,57.98 46.76,38.11 47.12,37.76 49.61,37.76 50.05,37.31 50.05,27.43 54.48,23 54.48,19.28 v2(56.07,17.69)
GMAC0_TXD2: length 81.9
  TOP w0.173: J1.78 v2(57.67,17.69) ; U3.16 47.82,77.67 v1(47.52,77.37)
  BOTTOM w0.173: v2(57.67,17.69) 57.29,17.31 55.65,17.31 53.98,18.98 53.98,22.75 49.52,27.2 49.52,36.36 49.04,36.84 46.15,36.84 45.87,37.12 45.87,57.32 45.57,57.62 42.78,57.62 42.39,58.01 42.39,67.17 42.67,67.45 42.67,69.73 42.47,69.93 42.16,69.93 41.96,70.13 41.96,70.42 42.16,70.62 42.47,70.62 42.67,70.82 42.67,71.11 42.47,71.31 42.16,71.31 41.96,71.51 41.96,71.8 42.16,72 42.47,72 42.67,72.2 42.67,73.44 42.47,73.64 42.11,73.64 41.91,73.84 41.91,76.29 42.45,76.83 46.98,76.83 v1(47.52,77.37)
GMAC0_TXD3: length 82.5
  TOP w0.173: v1(47.52,78.37) 47.82,78.07 U3.15 ; v2(56.07,16.85) 56.51,17.29 57.91,17.29 58.07,17.45 J1.80
  BOTTOM w0.173: v1(47.52,78.37) 46.51,77.36 42.04,77.36 41.27,76.6 41.27,67.58 41.81,67.05 41.81,57.49 42.26,57.04 44.42,57.04 44.78,56.68 44.78,36.21 45.09,35.91 48.69,35.91 49,35.6 49,26.84 53.45,22.39 53.45,18.68 55.27,16.85 v2(56.07,16.85)
GMAC0_TXEN: length 82
  TOP w0.173: J1.70 v2(56.07,20.46) ; v1(47.52,74.37) 47.96,74.81 47.96,75.62 48.81,76.47 U3.19
  BOTTOM w0.173: v2(56.07,20.46) 56.77,20.46 57,20.69 57,22.01 51.18,27.83 51.18,38.67 50.8,39.05 49.81,39.05 49.38,39.49 49.38,49.75 49.18,49.95 48.72,49.95 48.51,50.15 48.51,50.44 48.72,50.64 49.18,50.64 49.38,50.85 49.38,51.13 49.18,51.33 48.67,51.33 48.44,51.56 48.44,51.85 48.61,52.02 49.18,52.02 49.38,52.23 49.38,52.51 49.18,52.72 48.67,52.72 48.44,52.94 48.44,53.23 48.61,53.41 49.18,53.41 49.38,53.61 49.38,53.9 49.18,54.1 48.67,54.1 48.44,54.33 48.44,54.61 48.61,54.79 49.18,54.79 49.38,54.99 49.38,55.28 49.18,55.48 48.67,55.48 48.44,55.71 48.44,55.99 48.61,56.17 49.18,56.17 49.38,56.37 49.38,56.66 49.18,56.86 48.67,56.86 48.44,57.09 48.44,57.37 48.61,57.55 49.18,57.55 49.38,57.75 49.38,58.04 49.18,58.24 48.67,58.24 48.44,58.47 48.44,58.76 48.61,58.93 49.18,58.93 49.38,59.14 49.38,59.44 49.18,59.64 48.69,59.64 48.46,59.87 48.46,60.15 48.64,60.33 49.18,60.33 49.38,60.53 49.38,61.15 49.15,61.38 47.7,61.38 47.47,61.61 47.47,62.66 47.13,63.01 46.57,63.01 46.23,63.35 46.23,64.53 46,64.76 45.19,64.76 44.89,65.05 44.89,68.65 45.09,68.85 45.49,68.85 45.69,69.05 45.69,69.34 45.49,69.54 45.09,69.54 44.89,69.75 44.89,70.03 45.09,70.23 45.49,70.23 45.69,70.44 45.69,70.72 45.49,70.92 45.09,70.92 44.89,71.13 44.89,71.53 45.64,72.28 45.64,73.57 45.9,73.82 46.98,73.82 v1(47.52,74.37)
GMAC1_MCLKINOUT: length 74.1
  TOP w0.173: J1.67 55.67,33.08 56.74,34.15 65.94,34.15 v1(66.17,33.92)
  BOTTOM w0.173: R38.1 R37.1 75.44,74.26 73.56,72.38 73.56,65.83 74.19,65.19 74.19,57.34 73.53,56.68 73.53,44.46 73.05,43.98 66.57,43.98 66.17,43.58 v1(66.17,33.92)
GMAC1_MDC: length 77.4
  TOP w0.152: v1(62.23,26.69) 61.46,26.69 61.27,26.5 J1.95 ; v1(58.04,51.26) 58.28,51.5 66.09,51.5 66.45,51.86 66.45,68.11 66.14,68.42 64.67,68.42 64.44,68.65 64.44,72.86 63.91,73.4 63.91,79.87 64.4,80.37 v1(65.92,80.37) 65.92,80.02 66.47,79.47 66.47,79.14 66.74,78.87 U4.13
  BOTTOM w0.152: v1(58.04,51.26) 57.61,50.82 57.61,31.31 v1(62.23,26.69) ; R33.2 65.75,80.53 v1(65.92,80.37)
GMAC1_MDIO: length 76.3
  TOP w0.152: U4.14 66.46,78.47 65.92,79 v1(65.92,79.37) 64.54,79.37 64.36,79.19 64.36,73.7 64.8,73.27 64.8,69.1 65.05,68.85 66.62,68.85 66.93,68.54 66.93,51.35 66.62,51.04 58.83,51.04 v1(58.04,50.26) ; v1(63.23,26.69) 62.72,26.18 61.98,26.18 61.67,25.87 J1.97
  BOTTOM w0.152: v1(63.23,26.69) 58.04,31.88 v1(58.04,50.26) ; v1(65.92,79.37) 65.77,79.52 R34.2
GMAC1_RSTN: length 33.9
  TOP w0.152: J4.50 v1(77.64,69.61) ; U4.12 67.02,79.27 v1(66.92,79.37)
  ART03 w0.152: v1(77.65,83.5) 77.47,83.68 67.28,83.68 66.42,82.82 66.42,79.86 v1(66.92,79.37)
  BOTTOM w0.152: v1(77.64,69.61) 77.04,70.21 77.04,75.73 77.55,76.24 77.55,78.48 77.72,78.65 77.72,83.43 v1(77.65,83.5) ; v1(66.92,79.37) 67.07,79.52 C37.1 67.69,79.51 R41.2
GMAC1_RXCLK: length 65.9
  TOP w0.173: R28.1 v1(71.06,71.01) ; J1.85 59.27,29.34 59.62,29.69 v1(61.23,29.69)
  BOTTOM w0.173: R31.1 71.12,71.07 v1(71.06,71.01) 71.06,70.52 71.47,70.12 72.39,70.12 72.77,69.74 72.77,65.42 73.38,64.81 73.38,57.7 72.87,57.19 72.87,45.76 72.54,45.43 66.06,45.43 65.53,44.9 65.53,29.8 64.88,29.16 61.76,29.16 v1(61.23,29.69)
GMAC1_RXD0: length 65.7
  TOP w0.173: R23.1 v1(69.03,71.01) ; J1.87 59.67,28.34 60.02,28.69 62.83,28.69 63.23,29.08 v1(63.23,30.69)
  BOTTOM w0.173: R20.2 69.09,71.07 v1(69.03,71.01) 69.39,70.64 69.39,68.94 69.74,68.59 70.52,68.59 70.87,68.25 70.87,63.75 71.07,63.55 71.43,63.55 71.63,63.35 71.63,63.06 71.43,62.86 71.07,62.86 70.87,62.66 70.87,62.37 71.07,62.17 71.43,62.17 71.63,61.97 71.63,61.68 71.43,61.48 71.07,61.48 70.87,61.28 70.87,60.99 71.07,60.79 71.43,60.79 71.63,60.59 71.63,47.13 71.25,46.75 64.81,46.75 64.47,46.41 64.47,31.03 64.12,30.69 v1(63.23,30.69)
GMAC1_RXD1: length 65.2
  TOP w0.173: J1.89 60.07,28.04 60.25,28.21 63.5,28.21 63.88,28.59 63.88,31.03 v1(63.23,31.69) ; R24.1 v1(68.01,71.01)
  BOTTOM w0.173: R21.2 67.94,71.07 v1(68.01,71.01) 68.01,70.28 68.76,69.53 68.76,66.59 70.26,65.09 70.26,60.16 70.46,59.96 70.82,59.96 71.02,59.75 71.02,59.47 70.82,59.27 70.46,59.27 70.26,59.06 70.26,58.78 70.46,58.57 70.82,58.57 71.02,58.37 71.02,58.09 70.82,57.88 70.46,57.88 70.26,57.68 70.26,57.4 70.46,57.19 70.82,57.19 71.02,56.99 71.02,47.88 70.67,47.54 64.29,47.54 63.9,47.15 63.9,32.35 v1(63.23,31.69)
GMAC1_RXD2: length 63.8
  TOP w0.173: v1(63.23,32.69) 64.04,32.69 64.39,32.34 64.39,28.03 64.04,27.69 60.65,27.69 60.47,27.51 J1.91 ; R26.1 v1(67,71.01)
  BOTTOM w0.173: v1(63.23,32.69) 63.37,32.82 63.37,48.73 63.68,49.04 69.38,49.04 69.72,49.38 69.72,53.96 69.93,54.16 70.26,54.16 70.46,54.36 70.46,54.65 70.26,54.85 69.93,54.85 69.72,55.05 69.72,55.35 69.93,55.56 70.21,55.56 70.41,55.76 70.41,56.04 70.21,56.25 69.93,56.25 69.62,56.55 69.62,64.76 68.07,66.31 68.07,69.22 R30.1 67.18,70.82 v1(67,71.01)
GMAC1_RXD3: length 64.4
  TOP w0.173: R27.1 v1(65.98,71.01) ; v1(62.23,33.69) 64.5,33.69 65.02,33.16 65.02,27.54 64.68,27.19 61.22,27.19 60.87,26.85 J1.93
  BOTTOM w0.173: R22.2 65.91,71.07 v1(65.98,71.01) 66.55,70.44 66.55,66.69 69.01,64.23 69.01,50.17 68.67,49.82 63.37,49.82 62.84,49.29 62.84,34.3 v1(62.23,33.69)
GMAC1_RXDV_CRS: length 65.5
  TOP w0.173: R29.1 v1(70.04,71.01) ; J1.83 58.87,29.82 59.22,30.16 61.75,30.16 v1(62.23,29.69)
  BOTTOM w0.173: v1(62.23,29.69) 64.34,29.69 65,30.34 65,45.69 65.34,46.04 71.7,46.04 72.14,46.47 72.14,68.88 71.79,69.23 70.39,69.23 70.04,69.58 v1(70.04,71.01) 70.1,71.07 R32.1
GMAC1_TXCLK: length 71.5
  TOP w0.173: v1(66.92,75.37) 66.92,75.44 67.54,76.07 U4.20 ; J1.69 56.07,32.72 57.04,33.69 v1(61.23,33.69)
  BOTTOM w0.173: v1(61.23,33.69) 61.37,33.82 61.37,51.02 61.54,51.2 65.36,51.2 65.53,51.37 65.53,53.1 65.74,53.3 66.02,53.3 66.22,53.1 66.22,51.22 66.45,50.99 66.75,50.99 66.93,51.17 66.93,61.66 65.07,63.51 65.07,73.55 65.28,73.75 66.27,73.75 66.48,73.96 66.48,74.92 v1(66.92,75.37)
GMAC1_TXD0: length 72.1
  TOP w0.173: J1.73 56.87,31.67 57.89,32.69 v1(61.23,32.69) ; v1(65.92,75.37) 65.92,75.74 66.42,76.24 66.42,76.39 66.89,76.87 U4.18
  BOTTOM w0.173: v1(61.23,32.69) 60.72,32.69 60.25,33.16 60.25,52.95 60.45,53.15 62.08,53.15 62.28,53.35 62.28,53.64 62.08,53.84 60.58,53.84 60.38,54.05 60.38,54.47 60.55,54.65 64.86,54.65 65.13,54.92 65.13,61.91 63.25,63.79 63.25,67.76 63.8,68.32 63.8,74.82 64.35,75.37 v1(65.92,75.37)
GMAC1_TXD1: length 72
  TOP w0.173: U4.17 66.68,77.27 65.92,76.5 v1(65.92,76.37) ; J1.75 57.27,31.38 58.06,32.17 61.74,32.17 v1(62.23,31.69)
  BOTTOM w0.173: v1(62.23,31.69) 61.74,32.17 60.3,32.17 59.72,32.76 59.72,54.76 60.44,55.49 64.12,55.49 64.47,55.83 64.47,60.7 62.64,62.52 62.64,68.06 63.07,68.49 63.07,70.42 62.59,70.91 62.59,74.66 64.3,76.37 v1(65.92,76.37)
GMAC1_TXD2: length 72.1
  TOP w0.173: U4.16 66.22,77.67 v1(65.92,77.37) ; v1(61.23,31.69) 58.34,31.69 57.67,31.02 J1.77
  BOTTOM w0.173: v1(65.92,77.37) 65.79,77.24 64.32,77.24 61.95,74.87 61.95,70.58 62.54,69.98 62.54,68.81 61.32,67.58 61.32,61.68 61.52,61.48 62.51,61.48 62.71,61.28 62.71,60.99 62.51,60.79 61.52,60.79 61.32,60.59 61.32,59.88 61.85,59.35 61.85,57.57 61.5,57.23 59.42,57.23 59.16,56.96 59.16,56.66 59.36,56.46 59.72,56.46 59.92,56.26 59.92,55.97 59.72,55.77 59.36,55.77 59.16,55.57 59.16,32.43 59.9,31.69 v1(61.23,31.69)
GMAC1_TXD3: length 71.9
  TOP w0.173: U4.15 66.22,78.07 v1(65.92,78.37) ; J1.79 58.07,30.66 58.62,31.21 61.71,31.21 v1(62.23,30.69)
  BOTTOM w0.173: v1(62.23,30.69) 61.79,31.13 59.56,31.13 58.6,32.1 58.6,58.98 58.94,59.32 60.36,59.32 60.71,59.67 60.71,67.91 60.33,68.29 60.33,70.25 60.93,70.86 60.93,75.58 61.37,76.01 62.31,76.01 64.11,77.82 65.37,77.82 v1(65.92,78.37)
GMAC1_TXEN: length 72.1
  TOP w0.173: U4.19 67.21,76.47 66.36,75.62 66.36,74.81 v1(65.92,74.37) ; v1(62.23,32.69) 61.73,33.19 57.43,33.19 56.47,32.23 J1.71
  BOTTOM w0.173: v1(62.23,32.69) 61.73,33.19 61.1,33.19 60.76,33.53 60.76,51.98 61.21,52.44 62.9,52.44 63.07,52.61 63.07,53.59 63.24,53.76 63.54,53.76 63.74,53.56 63.74,52.67 63.95,52.47 64.23,52.47 64.43,52.67 64.43,53.66 64.64,53.86 65.63,53.86 65.91,54.14 65.91,61.97 63.93,63.95 63.93,67.43 64.47,67.96 64.47,74.01 64.83,74.37 v1(65.92,74.37)
HDMI0_5V: length 22.5
  TOP w0.254: R152.1 82.56,77.59 v1(82.69,77.72)
  ART04 w0.254: J16.18 86.29,81.93 85.78,81.42 83.63,81.42 83.12,80.91 83.12,78.15 v1(82.69,77.72) 82.69,73.28 83.31,72.66 85.85,72.66 86.36,72.15 v1(86.36,71.01)
  ART04 w0.381: 85.71,84.65 J16.18 86.86,84.65
  BOTTOM w0.254: R155.1 v1(86.36,71.01)
  vias: v1(86.93,99.19) v1(86.93,98.19) v1(87.93,99.19) v1(87.93,98.19)
HDMI0_EARC+: length 23.4
  TOP w0.114: C139.2 86.53,78.31 arc(86.48,78.37) 86.47,78.45 86.47,78.59 arc(86.49,78.7) 86.55,78.79 D30.2 86.64,79.09 arc(86.62,79.2) 86.56,79.29 86.55,79.3 arc(86.49,79.39) 86.47,79.5 86.47,81.19 arc(86.33,81.53) 86,81.66 85.2,81.66 arc(84.85,81.52) 84.71,81.17 84.71,78.56 arc(84.64,78.4) 84.48,78.34 84.24,78.34 arc(84.08,78.4) 84.01,78.56 84.01,79.52 arc(83.86,79.9) 83.48,80.05 82.24,80.05 arc(81.95,80.34) 82.24,80.62 83.48,80.62 arc(83.86,80.78) 84.01,81.15 84.01,82.08 arc(84.1,82.31) 84.33,82.4 85.64,82.4 arc(85.97,82.54) 86.11,82.87 86.11,83.4 arc(86.15,83.61) 86.27,83.8 86.69,84.22 arc(86.82,84.4) 86.86,84.62 86.86,86.15 arc(86.82,86.37) 86.69,86.55 J16.14
HDMI0_EARC-: length 23.3
  TOP w0.114: v1(85.85,77.97) 86.17,78.28 arc(86.21,78.35) 86.23,78.43 86.23,78.59 arc(86.21,78.7) 86.15,78.79 D27.2 86.05,79.09 arc(86.07,79.2) 86.13,79.29 86.15,79.3 arc(86.21,79.39) 86.23,79.5 86.23,81.19 arc(86.16,81.36) 86,81.42 85.2,81.42 arc(85.02,81.35) 84.95,81.17 84.95,78.56 arc(84.81,78.23) 84.48,78.09 84.24,78.09 arc(83.91,78.23) 83.77,78.56 83.77,79.52 arc(83.69,79.72) 83.48,79.81 82.24,79.81 arc(81.71,80.34) 82.24,80.86 83.48,80.86 arc(83.69,80.95) 83.77,81.15 83.77,82.08 arc(83.93,82.48) 84.33,82.64 85.64,82.64 arc(85.8,82.71) 85.86,82.87 85.86,83.22 arc(85.82,83.32) 85.73,83.36 84.43,83.36 arc(84.27,83.43) 84.2,83.59 84.2,84.29 arc(84.27,84.45) 84.43,84.52 85.06,84.52 arc(85.22,84.46) 85.29,84.3 J16.19
HDMI0_TX_ON: length 23.1
  TOP w0.152: J4.89 85.64,63.92 v2(85.24,63.52)
  BOTTOM w0.152: R169.1 103.64,64.01 103.3,63.67 89.2,63.67 87.88,64.99 85.95,64.99 85.65,64.68 85.65,64.54 85.65,64.54 85.65,64.18 85.65,64.17 85.65,63.93 v2(85.24,63.52)
HDMI1_5V: length 32.8
  ART04 w0.254: v1(108.71,71.21) 105.82,71.21 105.31,71.72 105.31,76.68 104.65,77.34 98.63,77.34 98.12,77.85 98.12,81.05 97.09,82.08 J17.18
  BOTTOM w0.254: R176.1 114.68,70.74 114.35,70.41 109.52,70.41 v1(108.71,71.21) 107.48,71.21 R173.1
  vias: v1(95.47,99.22) v1(95.47,98.22) v1(96.47,99.22) v1(96.47,98.22)
HDMI1_EARC+: length 14.1
  TOP w0.114: J17.14 97.63,86.41 arc(97.86,86.07) 97.94,85.66 97.94,84.82 arc(97.85,84.36) 97.59,83.96 97.24,83.62 arc(97.08,83.38) 97.03,83.1 97.03,82.98 arc(96.89,82.65) 96.56,82.51 96.35,82.51 arc(96.19,82.45) 96.13,82.28 96.13,82.27 arc(96.19,82.12) 96.34,82.06 96.59,82.06 arc(96.9,81.93) 97.03,81.62 97.03,81.43 arc(97.1,81.26) 97.27,81.19 98.84,81.19 arc(99.31,80.72) 98.84,80.25 98.16,80.25 arc(98,80.18) 97.94,80.02 97.94,79.46 arc(97.95,79.38) 98,79.31 98.03,79.28 arc(98.08,79.2) 98.1,79.1 D37.2 98,78.79 arc(97.94,78.7) 97.92,78.59 97.92,78.43 arc(97.94,78.35) 97.98,78.28 C151.2
